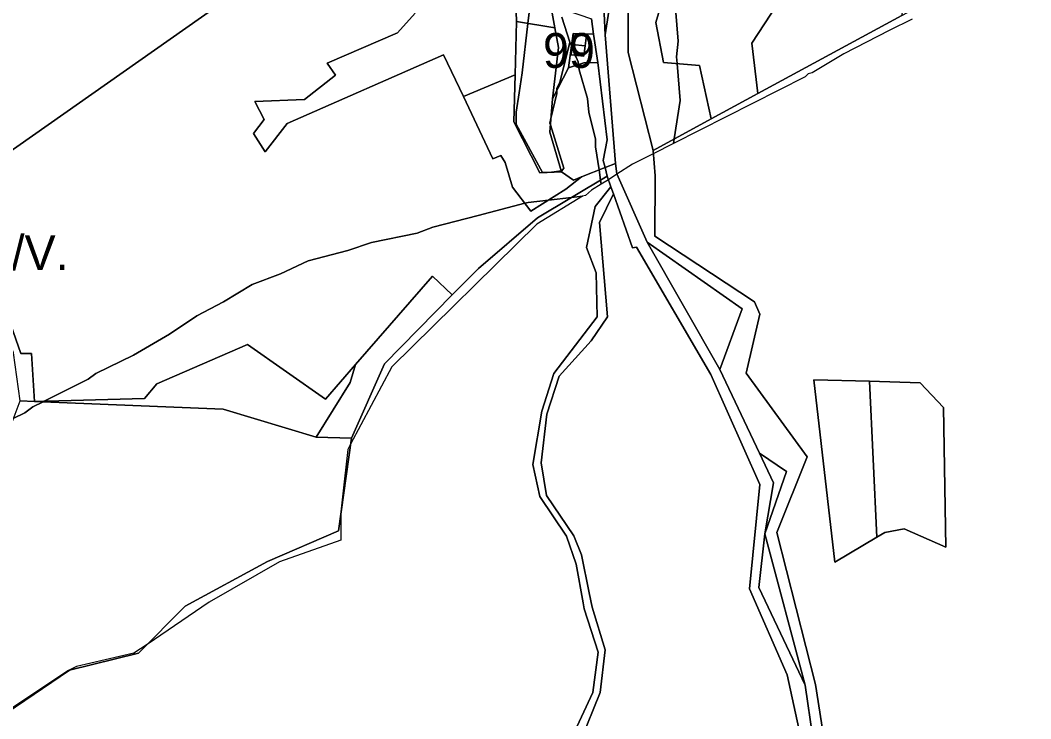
# Model space of a CAD drawing. Extents: x -477304 to -465429, y -1159113 to -1149210.
# Drawn here: x -472357.9 to -471923.8, y -1156987 to -1156686.8 of the extents above; entities that cross this region are included whole.
import ezdxf

# ---------------------------------------------------------------- set-up
doc = ezdxf.new("R2010")
doc.units = 0
for name, color, linetype in [('BPEJ_s', 7, 'Continuous'), ('ostatni_s', 7, 'Continuous'), ('PUPFL_s', 7, 'Continuous'), ('trav_porost_s', 7, 'Continuous'), ('voda_s', 7, 'Continuous')]:
    doc.layers.add(name, color=color, linetype=linetype)

msp = doc.modelspace()

# ---------------------------------------------------------------- linework, layer by layer
at = {"layer": 'BPEJ_s'}
for points in [[(-472138.71, -1156678.78), (-472139.82, -1156688.21), (-472142.32, -1156709.41), (-472143.61, -1156718), (-472144.88, -1156726.42), (-472144.88, -1156731.53), (-472133.56, -1156752.35), (-472129.69, -1156752.19), (-472129.57, -1156752.16), (-472125.58, -1156751.56), (-472125.31, -1156751.52), (-472124.46, -1156750.46), (-472130.18, -1156731.85), (-472130.41, -1156731.1), (-472129.94, -1156729.08), (-472127.44, -1156718.34), (-472127.44, -1156717.14), (-472127.44, -1156716), (-472126.16, -1156713.66), (-472121.82, -1156696.29), (-472121.16, -1156697.88), (-472120.93, -1156698.41), (-472119.46, -1156701.94), (-472119.13, -1156702.73), (-472118.29, -1156704.73), (-472118.14, -1156705.92), (-472117.99, -1156707.18), (-472117.87, -1156708.13), (-472114.25, -1156720.47), (-472113.61, -1156726.42), (-472110.85, -1156737.91), (-472110.85, -1156741.31), (-472109.27, -1156751.19), (-472108.57, -1156755.57), (-472108.29, -1156757.34), (-472112.55, -1156759.81), (-472115.1, -1156762.15), (-472116.37, -1156762.45), (-472121.05, -1156762.99), (-472131.01, -1156764.13), (-472139.77, -1156765.13), (-472141.12, -1156765.48), (-472161.14, -1156770.7), (-472180.61, -1156775.77), (-472187.41, -1156778.32), (-472206.98, -1156782.36), (-472217.19, -1156785.76), (-472234.2, -1156790.23), (-472246.11, -1156795.76), (-472258.23, -1156800.44), (-472270.57, -1156807.88), (-472282.05, -1156813.83), (-472293.75, -1156821.7), (-472309.28, -1156830.85), (-472325.44, -1156838.72), (-472328.63, -1156841.06), (-472347.57, -1156850.53), (-472348.1, -1156850.79), (-472352.45, -1156852.97), (-472355.85, -1156855.52), (-472360.86, -1156858.06)], [(-472125.31, -1156685.59), (-472121.82, -1156696.29), (-472126.16, -1156713.66), (-472127.44, -1156716), (-472127.44, -1156717.14), (-472127.44, -1156718.34), (-472129.94, -1156729.08), (-472130.41, -1156731.1), (-472130.18, -1156731.85), (-472124.46, -1156750.46), (-472125.31, -1156751.52), (-472125.58, -1156751.56), (-472129.57, -1156752.16), (-472129.69, -1156752.19), (-472133.56, -1156752.35), (-472144.88, -1156731.53), (-472144.88, -1156726.42), (-472143.61, -1156718), (-472142.32, -1156709.41), (-472139.82, -1156688.21), (-472138.71, -1156678.78)], [(-472076.39, -1156681.76), (-472075.33, -1156695.8), (-472075.97, -1156702.6), (-472075.74, -1156705.47), (-472074.48, -1156721.32), (-472077.02, -1156737.88), (-472077.33, -1156739.89), (-472085.95, -1156744.24), (-472094.9, -1156748.76), (-472101.57, -1156753.03), (-472105.25, -1156755.39), (-472108.29, -1156757.34), (-472108.57, -1156755.57), (-472109.27, -1156751.19), (-472110.85, -1156741.31), (-472110.85, -1156737.91), (-472113.61, -1156726.42), (-472114.25, -1156720.47), (-472117.87, -1156708.13), (-472117.99, -1156707.18), (-472118.14, -1156705.92), (-472118.29, -1156704.73), (-472119.13, -1156702.73), (-472119.46, -1156701.94), (-472120.93, -1156698.41), (-472121.16, -1156697.88), (-472121.82, -1156696.29), (-472125.31, -1156685.59)], [(-471974.74, -1156686.44), (-471984.66, -1156691.29), (-472004.08, -1156701.33), (-472017.69, -1156709.41), (-472019.4, -1156709.84), (-472020.67, -1156711.11), (-472077.33, -1156739.89), (-472077.02, -1156737.88), (-472074.48, -1156721.32), (-472075.74, -1156705.47), (-472075.97, -1156702.6), (-472075.33, -1156695.8), (-472076.39, -1156681.76)], [(-471974.74, -1156686.44), (-471984.66, -1156691.29), (-472004.08, -1156701.33), (-472017.69, -1156709.41), (-472019.4, -1156709.84), (-472020.67, -1156711.11), (-472077.33, -1156739.89), (-472085.95, -1156744.24), (-472094.9, -1156748.76), (-472101.57, -1156753.03), (-472105.25, -1156755.39), (-472108.29, -1156757.34), (-472112.55, -1156759.81), (-472115.1, -1156762.15), (-472116.37, -1156762.45), (-472135.94, -1156774.49)], [(-472116.37, -1156762.45), (-472135.94, -1156774.49), (-472198.26, -1156835.74), (-472215.96, -1156868.96), (-472217.19, -1156871.26), (-472218.74, -1156885.27), (-472220.16, -1156898.05), (-472220.17, -1156899.22), (-472220.24, -1156910.32), (-472246.54, -1156919.54), (-472276.74, -1156936.97), (-472303.41, -1156955.05), (-472309.06, -1156958.88), (-472333.73, -1156964.62), (-472337.14, -1156966.32), (-472354.15, -1156977.59), (-472368.61, -1156987.17)], [(-472360.86, -1156858.06), (-472355.85, -1156855.52), (-472352.45, -1156852.97), (-472348.1, -1156850.79), (-472347.57, -1156850.53), (-472328.63, -1156841.06), (-472325.44, -1156838.72), (-472309.28, -1156830.85), (-472293.75, -1156821.7), (-472282.05, -1156813.83), (-472270.57, -1156807.88), (-472258.23, -1156800.44), (-472246.11, -1156795.76), (-472234.2, -1156790.23), (-472217.19, -1156785.76), (-472206.98, -1156782.36), (-472187.41, -1156778.32), (-472180.61, -1156775.77), (-472161.14, -1156770.7), (-472141.12, -1156765.48), (-472139.77, -1156765.13), (-472131.01, -1156764.13), (-472121.05, -1156762.99), (-472116.37, -1156762.45)], [(-472135.94, -1156774.49), (-472198.26, -1156835.74), (-472215.96, -1156868.96), (-472217.19, -1156871.26), (-472218.74, -1156885.27), (-472220.16, -1156898.05), (-472220.17, -1156899.22), (-472220.24, -1156910.32), (-472246.54, -1156919.54), (-472276.74, -1156936.97), (-472303.41, -1156955.05), (-472309.06, -1156958.88), (-472333.73, -1156964.62), (-472337.14, -1156966.32), (-472354.15, -1156977.59), (-472368.61, -1156987.17)]]:
    msp.add_lwpolyline(points, dxfattribs=at)
at = {"layer": 'ostatni_s'}
for points in [[(-472143.33, -1156666.34), (-472137.46, -1156654.61), (-472130.33, -1156654.7), (-472130.65, -1156676.53), (-472128.26, -1156690.13), (-472144.69, -1156687.4), (-472145.29, -1156670.53)], [(-472123.32, -1156682.48), (-472112.55, -1156686.28), (-472111.6, -1156692.82), (-472120.45, -1156692.5), (-472122.39, -1156707.3), (-472129.2, -1156720.58), (-472126.68, -1156698.62), (-472128.26, -1156690.13), (-472130.65, -1156676.53), (-472130.33, -1156654.7)], [(-472106, -1156655.84), (-472103.07, -1156658.98), (-472101.59, -1156660.57), (-472106.6, -1156693.17), (-472108.48, -1156653.16)], [(-472120.45, -1156692.5), (-472111.6, -1156692.82), (-472109.82, -1156705.06), (-472115.73, -1156705.13), (-472122.39, -1156707.3)], [(-472114.7, -1156693.34), (-472120.33, -1156692.74), (-472120.81, -1156697.24), (-472121.29, -1156701.75), (-472115.75, -1156702.34), (-472115.23, -1156697.84)], [(-472115.23, -1156697.84), (-472120.81, -1156697.24), (-472120.33, -1156692.74), (-472114.7, -1156693.34)], [(-472115.23, -1156697.84), (-472115.75, -1156702.34), (-472121.29, -1156701.75), (-472120.81, -1156697.24)], [(-472125.45, -1156752.02), (-472130.45, -1156734.89), (-472129.2, -1156720.58), (-472122.39, -1156707.3), (-472115.73, -1156705.13), (-472109.82, -1156705.06), (-472105.8, -1156738.27), (-472107.44, -1156747.12), (-472106.65, -1156750.16), (-472116.85, -1156754.18), (-472120.23, -1156755.51)], [(-472357.62, -1156830), (-472352.97, -1156830.05), (-472351.8, -1156850.64), (-472357.97, -1156850.39), (-472360.81, -1156829.71), (-472371.34, -1156800.62), (-472389.42, -1156776.33), (-472384.69, -1156774.37), (-472368.5, -1156799.23)], [(-472016.98, -1156841.32), (-471993.16, -1156841.99), (-471989.94, -1156909.05), (-472007.96, -1156919.68)], [(-472038.08, -1156907.56), (-472034.3, -1156885.69), (-472040.39, -1156872.85), (-472028.73, -1156880.71)]]:
    msp.add_lwpolyline(points, close=True, dxfattribs=at)
for points in [[(-472108.48, -1156653.16), (-472106.6, -1156693.17), (-472102.13, -1156748.38), (-472106.65, -1156750.16), (-472107.44, -1156747.12), (-472105.8, -1156738.27), (-472109.82, -1156705.06), (-472111.6, -1156692.82), (-472112.55, -1156686.28)], [(-472017.4, -1157018.9), (-472028.48, -1156968.14), (-472044.67, -1156931.16), (-472040.15, -1156886.39), (-472061.29, -1156839.12), (-472093.22, -1156784.34), (-472094.92, -1156784.65), (-472103.09, -1156761.52), (-472104.17, -1156758.45), (-472105.77, -1156753.91), (-472106.65, -1156750.16), (-472102.13, -1156748.38), (-472101.66, -1156752.84), (-472088.59, -1156782.23), (-472057.38, -1156837.01), (-472040.39, -1156872.85), (-472034.3, -1156885.69), (-472038.08, -1156907.56), (-472040.64, -1156930.59), (-472020.76, -1156972.6), (-472014.15, -1157017.88)], [(-472120.66, -1156994.46), (-472111.98, -1156975.72), (-472109.66, -1156958.42), (-472115.64, -1156939.74), (-472116.1, -1156937.17), (-472119.06, -1156920.54), (-472123.24, -1156908.61), (-472134.67, -1156891.58), (-472137.65, -1156877.79), (-472133.84, -1156854.82), (-472128.66, -1156838.67), (-472110.02, -1156814.3), (-472110.56, -1156795.45), (-472114.67, -1156784.55), (-472110.92, -1156766.84), (-472104.17, -1156758.45), (-472103.09, -1156761.52), (-472109.01, -1156773.78), (-472105.67, -1156814.35), (-472112.69, -1156824.65), (-472126.34, -1156839.84), (-472131.62, -1156856.16), (-472134.18, -1156877.11), (-472131.9, -1156891.12), (-472120.14, -1156908.39), (-472116.84, -1156916.62), (-472113.51, -1156932.89), (-472112.25, -1156939.06), (-472106.65, -1156957.43), (-472108.79, -1156975.73), (-472117.22, -1156996.68)]]:
    msp.add_lwpolyline(points, dxfattribs=at)
at = {"layer": 'PUPFL_s'}
for points in [[(-472009.29, -1157017.07), (-472016.29, -1156972.29), (-472032.83, -1156906.94), (-472019.87, -1156874.51), (-472046.09, -1156838.47), (-472040.21, -1156813.22), (-472042.52, -1156807.9), (-472085.31, -1156779.68), (-472085.22, -1156753.67), (-472086.06, -1156742.79), (-472061.12, -1156729.25), (-472041.06, -1156718.36), (-471979.2, -1156684.75), (-471755.96, -1156566.41), (-471629.22, -1156596.63), (-471380.96, -1156656.46), (-471425.12, -1156711.66), (-471521.34, -1156831.93), (-471583.75, -1156909.94), (-471588.76, -1156916.21), (-471596.01, -1156925.27), (-471582, -1156972.2), (-471577.84, -1156986.15), (-471570.53, -1157010.66)], [(-472382.8, -1156997.43), (-472336.68, -1156966.17), (-472307.14, -1156958.77), (-472287.03, -1156938.71), (-472251.67, -1156919.39), (-472221.16, -1156906.32), (-472215.62, -1156866.51), (-472201.43, -1156834.44), (-472172.42, -1156804.84), (-472161.09, -1156793.53), (-472135.75, -1156771.72), (-472105.77, -1156753.91), (-472104.17, -1156758.45), (-472110.92, -1156766.84), (-472114.67, -1156784.55), (-472110.56, -1156795.45), (-472110.02, -1156814.3), (-472128.66, -1156838.67), (-472133.84, -1156854.82), (-472137.65, -1156877.79), (-472134.67, -1156891.58), (-472123.24, -1156908.61), (-472119.06, -1156920.54), (-472116.1, -1156937.17), (-472115.64, -1156939.74), (-472109.66, -1156958.42), (-472111.98, -1156975.72), (-472120.66, -1156994.46)], [(-472117.22, -1156996.68), (-472108.79, -1156975.73), (-472106.65, -1156957.43), (-472112.25, -1156939.06), (-472113.51, -1156932.89), (-472116.84, -1156916.62), (-472120.14, -1156908.39), (-472131.9, -1156891.12), (-472134.18, -1156877.11), (-472131.62, -1156856.16), (-472126.34, -1156839.84), (-472112.69, -1156824.65), (-472105.67, -1156814.35), (-472109.01, -1156773.78), (-472103.09, -1156761.52), (-472094.92, -1156784.65), (-472093.22, -1156784.34), (-472061.29, -1156839.12), (-472040.15, -1156886.39), (-472044.67, -1156931.16), (-472028.48, -1156968.14), (-472017.4, -1157018.9)]]:
    msp.add_lwpolyline(points, dxfattribs=at)
for points in [[(-472081.54, -1156704.97), (-472066.16, -1156706.31), (-472061.12, -1156729.25), (-472086.06, -1156742.79), (-472096.81, -1156700.67), (-472096.94, -1156664.76), (-472094.72, -1156660.51), (-472089.53, -1156662.5), (-472070.79, -1156639.17), (-472068.16, -1156647.23), (-472078.32, -1156665.55), (-472084.93, -1156687.78)], [(-472084.93, -1156687.78), (-472078.32, -1156665.55), (-472068.16, -1156647.23), (-472053.43, -1156645.69), (-472037.77, -1156640.52), (-472027.65, -1156672.06), (-472043.63, -1156696.7), (-472041.06, -1156718.36), (-472061.12, -1156729.25), (-472066.16, -1156706.31), (-472081.54, -1156704.97)], [(-472043.63, -1156696.7), (-472027.65, -1156672.06), (-471992.98, -1156677.59), (-471977.6, -1156664.19), (-471979.2, -1156684.75), (-472041.06, -1156718.36)], [(-472125.45, -1156752.02), (-472134.71, -1156752.4), (-472145.82, -1156730.49), (-472145.27, -1156710.26), (-472144.69, -1156687.4), (-472128.26, -1156690.13), (-472126.68, -1156698.62), (-472129.2, -1156720.58), (-472130.45, -1156734.89)], [(-472088.59, -1156782.23), (-472047.84, -1156810.91), (-472057.38, -1156837.01)], [(-472216.1, -1156842.5), (-472213.91, -1156834.73), (-472180.78, -1156796.84), (-472172.42, -1156804.84), (-472201.43, -1156834.44), (-472215.62, -1156866.51), (-472230.8, -1156865.95)], [(-472304.47, -1156849.4), (-472299.21, -1156843.17), (-472260.22, -1156826.26), (-472226.72, -1156849.67), (-472213.91, -1156834.73), (-472216.1, -1156842.5), (-472230.8, -1156865.95), (-472270.77, -1156853.98), (-472351.8, -1156850.64)], [(-472007.96, -1156919.68), (-471989.94, -1156909.05), (-471986.49, -1156907.01), (-471978.14, -1156905.42), (-471960.32, -1156913.22), (-471961.38, -1156853.21), (-471971.32, -1156842.6), (-471993.16, -1156841.99), (-472016.98, -1156841.32)], [(-471971.32, -1156842.6), (-471961.38, -1156853.21), (-471960.32, -1156913.22), (-471978.14, -1156905.42), (-471986.49, -1156907.01), (-471989.94, -1156909.05), (-471993.16, -1156841.99)], [(-472476.37, -1156975.29), (-472460.19, -1156975.26), (-472426.99, -1156959.38), (-472415.58, -1156949.24), (-472394.67, -1156915.11), (-472375.46, -1156896.76), (-472369.2, -1156880.22), (-472357.97, -1156850.39), (-472351.8, -1156850.64), (-472270.77, -1156853.98), (-472230.8, -1156865.95), (-472215.62, -1156866.51), (-472221.16, -1156906.32), (-472251.67, -1156919.39), (-472287.03, -1156938.71), (-472307.14, -1156958.77), (-472336.68, -1156966.17), (-472382.8, -1156997.43), (-472414.59, -1157035.96), (-472473.75, -1157053.08), (-472475.82, -1157019.69), (-472479.18, -1156975.3)], [(-472040.64, -1156930.59), (-472038.08, -1156907.56), (-472020.76, -1156972.6)]]:
    msp.add_lwpolyline(points, close=True, dxfattribs=at)
at = {"layer": 'trav_porost_s'}
for points in [[(-472373.99, -1156587.03), (-472357.34, -1156582.81), (-472321.7, -1156582.9), (-472304.37, -1156576.18), (-472300.06, -1156581.04), (-472291.78, -1156590.2), (-472299.39, -1156599.34), (-472278.42, -1156621.61), (-472276.82, -1156610.59), (-472276.21, -1156609.97), (-472248.28, -1156645.99), (-472236.8, -1156637.77), (-472232.94, -1156635.01), (-472227.65, -1156648.59), (-472366.12, -1156746.03)], [(-472366.12, -1156746.03), (-472227.65, -1156648.59)], [(-472145.29, -1156670.53), (-472144.69, -1156687.4), (-472145.27, -1156710.26), (-472167.55, -1156719.68), (-472176.11, -1156701.71), (-472243.24, -1156731.22), (-472252.73, -1156743.46), (-472257.62, -1156735.59), (-472253.1, -1156729.44), (-472257.17, -1156721.79), (-472235.82, -1156720.93), (-472222.45, -1156710.51), (-472226.07, -1156705.37), (-472195.77, -1156692.25), (-472188.25, -1156683.82)], [(-472188.25, -1156683.82), (-472195.77, -1156692.25), (-472226.07, -1156705.37), (-472222.45, -1156710.51), (-472235.82, -1156720.93), (-472257.17, -1156721.79), (-472253.1, -1156729.44), (-472257.62, -1156735.59), (-472252.73, -1156743.46), (-472243.24, -1156731.22), (-472176.11, -1156701.71), (-472167.55, -1156719.68), (-472154.83, -1156746.39), (-472151.38, -1156745), (-472149.52, -1156748), (-472146.39, -1156758.53), (-472138.54, -1156768.88), (-472123.51, -1156759.4), (-472116.85, -1156754.18), (-472106.65, -1156750.16), (-472105.77, -1156753.91), (-472135.75, -1156771.72), (-472161.09, -1156793.53), (-472172.42, -1156804.84), (-472180.78, -1156796.84), (-472213.91, -1156834.73), (-472226.72, -1156849.67), (-472260.22, -1156826.26), (-472299.21, -1156843.17), (-472304.47, -1156849.4), (-472351.8, -1156850.64), (-472352.97, -1156830.05), (-472357.62, -1156830), (-472368.5, -1156799.23)]]:
    msp.add_lwpolyline(points, dxfattribs=at)
msp.add_lwpolyline([(-472120.23, -1156755.51), (-472116.85, -1156754.18), (-472123.51, -1156759.4), (-472138.54, -1156768.88), (-472146.39, -1156758.53), (-472149.52, -1156748), (-472151.38, -1156745), (-472154.83, -1156746.39), (-472167.55, -1156719.68), (-472145.27, -1156710.26), (-472145.82, -1156730.49), (-472134.71, -1156752.4), (-472125.45, -1156752.02)], close=True, dxfattribs=at)
at = {"layer": 'voda_s'}
for points in [[(-472014.15, -1157017.88), (-472020.76, -1156972.6), (-472038.08, -1156907.56), (-472028.73, -1156880.71), (-472040.39, -1156872.85), (-472057.38, -1156837.01), (-472047.84, -1156810.91), (-472088.59, -1156782.23), (-472101.66, -1156752.84), (-472102.13, -1156748.38), (-472106.6, -1156693.17), (-472101.59, -1156660.57)], [(-472096.94, -1156664.76), (-472096.81, -1156700.67), (-472086.06, -1156742.79), (-472085.22, -1156753.67), (-472085.31, -1156779.68), (-472042.52, -1156807.9), (-472040.21, -1156813.22), (-472046.09, -1156838.47), (-472019.87, -1156874.51), (-472032.83, -1156906.94), (-472016.29, -1156972.29), (-472009.29, -1157017.07)]]:
    msp.add_lwpolyline(points, dxfattribs=at)

# ---------------------------------------------------------------- texts
at = {"layer": 'BPEJ_s'}
for s, p in [('99', (-472133.35, -1156707.35)), ('84168/V.', (-472417.38, -1156794.24))]:
    msp.add_text(s, height=15, dxfattribs=at).set_placement(p)

doc.saveas('drawing.dxf')
